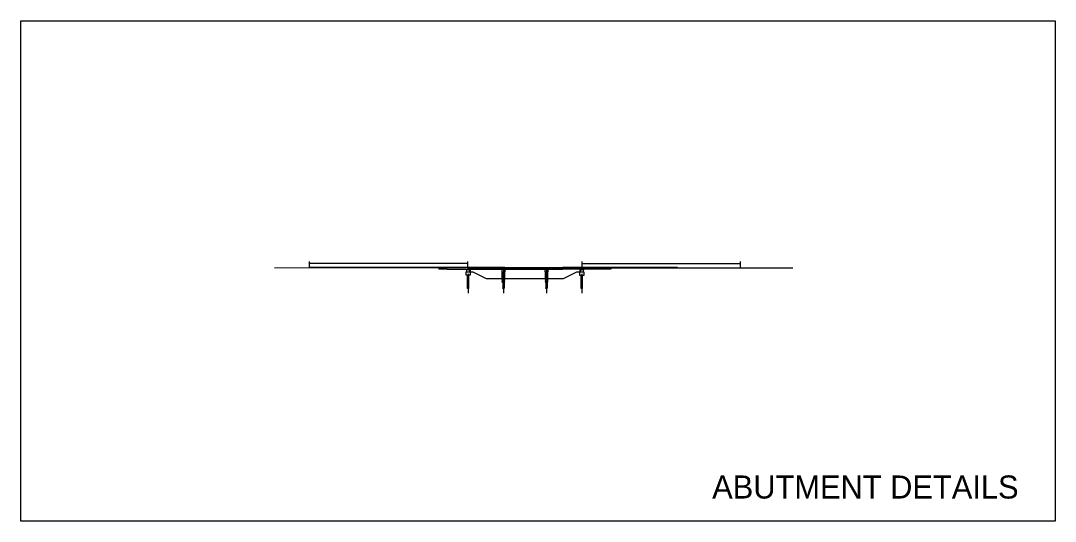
# Model space of a CAD drawing. Extents: x -2063 to 2068, y 79 to 1202.
# Drawn here: x 1170 to 2068, y 79 to 513 of the extents above; entities that cross this region are included whole.
import ezdxf

# ---------------------------------------------------------------- set-up
doc = ezdxf.new("R2010")
doc.units = 0
for name, color, linetype in [('BR_P_Gen_Joint_Filler', 7, 'Continuous'), ('BR_P_Slab_Object', 7, 'Continuous'), ('BR_X_Brg_Centerline', 7, 'Continuous'), ('BR_X_Gen_Approach_Slab', 7, 'Continuous'), ('BR_X_Slab_Object', 7, 'Continuous'), ('BR_X_Sub_Deep_Centerline', 7, 'Continuous'), ('BR_X_Sub_Deep_Object', 7, 'Continuous'), ('BR_X_Sub_Object', 7, 'Continuous'), ('PF_X_Ground_Line', 7, 'Continuous'), ('SC_Scratch1', 7, 'Continuous'), ('XS_P_Pavt_Surface', 7, 'Continuous')]:
    doc.layers.add(name, color=color, linetype=linetype)

msp = doc.modelspace()

# ---------------------------------------------------------------- linework, layer by layer
at = {"layer": 'BR_P_Gen_Joint_Filler'}
msp.add_line((1558.52, 298.6), (1558.67, 298.6), dxfattribs=at)
for points in [[(1558.46, 298.62), (1558.5, 298.62), (1558.5, 298.45), (1558.46, 298.45)], [(1657.78, 298.59), (1657.74, 298.59), (1657.74, 298.42), (1657.78, 298.42)]]:
    msp.add_lwpolyline(points, close=True, dxfattribs=at)
at = {"layer": 'BR_P_Slab_Object'}
for p, q in [((1558.52, 298.64), (1558.5, 298.62)), ((1558.5, 298.45), (1558.5, 298.62)), ((1657.72, 298.61), (1657.74, 298.59)), ((1657.74, 298.59), (1657.74, 298.42))]:
    msp.add_line(p, q, dxfattribs=at)
for points in [[(1640.62, 298.44), (1590.62, 298.46), (1558.5, 298.45)], [(1558.52, 298.64), (1590.62, 298.65), (1640.62, 298.63)]]:
    msp.add_lwpolyline(points, dxfattribs=at)
for centre, start in [((1635.98, -11316.67), 89.892735), ((1635.98, -11316.86), 89.892632)]:
    msp.add_arc(centre, 11615.3, start, 89.977082, dxfattribs=at)
at = {"layer": 'BR_X_Brg_Centerline'}
for p, q in [((1559.37, 299.37), (1559.37, 296.27)), ((1589.37, 298.1), (1589.37, 276.39)), ((1626.87, 298.08), (1626.87, 276.39)), ((1656.88, 299.35), (1656.88, 296.24))]:
    msp.add_line(p, q, dxfattribs=at)
at = {"layer": 'BR_X_Gen_Approach_Slab'}
for p, q in [((1533.5, 298.52), (1533.5, 297.44)), ((1558.5, 298.53), (1540.62, 298.53)), ((1540.62, 297.44), (1556.64, 297.45)), ((1556.64, 297.45), (1557.06, 297.03)), ((1557.06, 297.03), (1557.64, 297.03)), ((1682.74, 298.47), (1682.74, 297.39))]:
    msp.add_line(p, q, dxfattribs=at)
msp.add_lwpolyline([(1659.6, 297.42), (1659.19, 297.01), (1658.61, 297.01)], dxfattribs=at)
for centre, start, end in [((1603.12, -62201.63), 90.0572958, 90.0638229), ((1603.12, -62202.71), 90.0572958, 90.0638229), ((1578.12, -62201.63), 89.9040915, 89.9270098), ((1578.12, -62202.71), 89.9040915, 89.9253092)]:
    msp.add_arc(centre, 62500.19, start, end, dxfattribs=at)
at = {"layer": 'BR_X_Slab_Object'}
for p, q in [((1558.5, 298.53), (1558.5, 297.24)), ((1657.74, 297.22), (1657.74, 298.51))]:
    msp.add_line(p, q, dxfattribs=at)
for points in [[(1640.62, 298.61), (1590.62, 298.63), (1558.5, 298.62)], [(1640.62, 298.53), (1590.62, 298.55), (1558.5, 298.53)], [(1558.5, 298.51), (1590.62, 298.53), (1640.62, 298.51)], [(1640.62, 298.44), (1590.62, 298.46), (1558.5, 298.45)], [(1560.52, 297.24), (1590.62, 297.25), (1640.62, 297.23)]]:
    msp.add_lwpolyline(points, dxfattribs=at)
for centre, radius, start in [((1578.12, -62201.63), 62500.27, 89.9270099), ((1578.12, -62201.63), 62500.19, 89.9270098), ((1578.12, -62201.63), 62500.17, 89.9270098), ((1578.12, -62201.63), 62500.1, 89.9270097), ((1578.12, -62202.92), 62500.19, 89.9288623)]:
    msp.add_arc(centre, radius, start, 89.9427042, dxfattribs=at)
at = {"layer": 'BR_X_Sub_Deep_Centerline'}
for p, q in [((1558.79, 293.16), (1558.79, 276.39)), ((1657.45, 293.13), (1657.45, 276.39))]:
    msp.add_line(p, q, dxfattribs=at)
at = {"layer": 'BR_X_Sub_Deep_Object'}
for p, q in [((1558.21, 280.79), (1558.21, 291.97)), ((1559.38, 280.79), (1559.38, 291.97)), ((1588.79, 294.98), (1588.79, 280.79)), ((1589.96, 294.98), (1589.96, 280.79)), ((1626.29, 294.97), (1626.29, 280.79)), ((1627.46, 294.97), (1627.46, 280.79)), ((1656.87, 280.76), (1656.87, 291.94)), ((1658.04, 280.76), (1658.04, 291.94))]:
    msp.add_line(p, q, dxfattribs=at)
for points in [[(1588.29, 294.98), (1588.37, 294.97), (1588.37, 294.91), (1588.19, 294.88), (1588.19, 294.81), (1588.37, 294.78), (1588.37, 294.71), (1588.19, 294.68), (1588.19, 294.61), (1588.37, 294.58), (1588.37, 294.52), (1588.19, 294.49), (1588.19, 294.42), (1588.37, 294.39), (1588.37, 294.33), (1588.19, 294.3), (1588.19, 294.23), (1588.37, 294.2), (1588.37, 294.14), (1588.19, 294.11), (1588.19, 294.04), (1588.37, 294.01), (1588.37, 293.94), (1588.19, 293.91), (1588.19, 293.84), (1588.37, 293.81), (1588.37, 293.75), (1588.19, 293.72), (1588.19, 293.65), (1588.37, 293.62), (1588.37, 293.56), (1588.19, 293.53), (1588.19, 293.46), (1588.37, 293.43), (1588.37, 293.36), (1588.19, 293.33), (1588.19, 293.26), (1588.37, 293.23), (1588.37, 293.17), (1588.19, 293.14), (1588.19, 293.07), (1588.37, 293.04), (1588.37, 292.98), (1588.19, 292.95), (1588.19, 292.88), (1588.37, 292.85), (1588.37, 292.78), (1588.19, 292.75), (1588.19, 292.68), (1588.37, 292.65), (1588.37, 292.59), (1588.19, 292.56), (1588.19, 292.49), (1588.37, 292.46), (1588.37, 292.4), (1588.19, 292.37), (1588.19, 292.3), (1588.37, 292.27), (1588.37, 292.2), (1588.19, 292.17), (1588.19, 292.1), (1588.37, 292.07), (1588.37, 292.01), (1588.19, 291.98), (1588.19, 291.91), (1588.37, 291.88), (1588.37, 291.82), (1588.19, 291.79), (1588.19, 291.72), (1588.37, 291.69), (1588.37, 291.62), (1588.19, 291.59), (1588.19, 291.52), (1588.37, 291.49), (1588.37, 291.43), (1588.19, 291.4), (1588.19, 291.33), (1588.37, 291.3), (1588.37, 291.24), (1588.19, 291.21), (1588.19, 291.14), (1588.37, 291.11), (1588.37, 291.04), (1588.19, 291.01), (1588.19, 290.94), (1588.37, 290.91), (1588.37, 290.85), (1588.19, 290.82), (1588.19, 290.75), (1588.37, 290.72), (1588.37, 290.66), (1588.19, 290.63), (1588.19, 290.56), (1588.37, 290.53), (1588.37, 290.46), (1588.19, 290.43), (1588.19, 290.36), (1588.37, 290.33), (1588.37, 290.27), (1588.19, 290.24), (1588.19, 290.17), (1588.37, 290.14), (1588.37, 290.08), (1588.19, 290.05), (1588.19, 289.98), (1588.37, 289.95), (1588.37, 289.88), (1588.19, 289.85), (1588.19, 289.78), (1588.37, 289.75), (1588.37, 289.69), (1588.19, 289.66), (1588.19, 289.59), (1588.37, 289.56), (1588.37, 289.5), (1588.19, 289.47), (1588.19, 289.4), (1588.37, 289.37), (1588.37, 289.3), (1588.19, 289.27), (1588.19, 289.2), (1588.37, 289.17), (1588.37, 289.11), (1588.19, 289.08), (1588.19, 289.01), (1588.37, 288.98), (1588.37, 288.92), (1588.19, 288.89), (1588.19, 288.82), (1588.37, 288.79), (1588.37, 288.72), (1588.19, 288.69), (1588.19, 288.62), (1588.37, 288.59), (1588.37, 288.53), (1588.19, 288.5), (1588.19, 288.43), (1588.37, 288.4), (1588.37, 288.34), (1588.19, 288.31), (1588.19, 288.24), (1588.37, 288.21), (1588.37, 288.14), (1588.19, 288.11), (1588.19, 288.04), (1588.37, 288.01), (1588.37, 287.95), (1588.19, 287.92), (1588.19, 287.85), (1588.37, 287.82), (1588.37, 287.76), (1588.19, 287.73), (1588.19, 287.66), (1588.37, 287.63), (1588.37, 287.56), (1588.19, 287.53), (1588.19, 287.46), (1588.37, 287.43), (1588.37, 287.37), (1588.19, 287.34), (1588.19, 287.27), (1588.37, 287.24), (1588.37, 287.18), (1588.19, 287.15), (1588.19, 287.08), (1588.37, 287.05), (1588.37, 286.98), (1588.19, 286.95), (1588.19, 286.88), (1588.37, 286.85), (1588.37, 286.79), (1588.19, 286.76), (1588.19, 286.69), (1588.37, 286.66), (1588.37, 286.6), (1588.19, 286.57), (1588.19, 286.5), (1588.37, 286.47), (1588.37, 286.4), (1588.19, 286.37), (1588.19, 286.3), (1588.37, 286.27), (1588.37, 286.21), (1588.19, 286.18), (1588.19, 286.17), (1590.55, 286.17), (1590.55, 286.18), (1590.37, 286.21), (1590.37, 286.27), (1590.55, 286.3), (1590.55, 286.37), (1590.37, 286.4), (1590.37, 286.47), (1590.55, 286.5), (1590.55, 286.57), (1590.37, 286.6), (1590.37, 286.66), (1590.55, 286.69), (1590.55, 286.76), (1590.37, 286.79), (1590.37, 286.85), (1590.55, 286.88), (1590.55, 286.95), (1590.37, 286.98), (1590.37, 287.05), (1590.55, 287.08), (1590.55, 287.15), (1590.37, 287.18), (1590.37, 287.24), (1590.55, 287.27), (1590.55, 287.34), (1590.37, 287.37), (1590.37, 287.43), (1590.55, 287.46), (1590.55, 287.53), (1590.37, 287.56), (1590.37, 287.63), (1590.55, 287.66), (1590.55, 287.73), (1590.37, 287.76), (1590.37, 287.82), (1590.55, 287.85), (1590.55, 287.92), (1590.37, 287.95), (1590.37, 288.01), (1590.55, 288.04), (1590.55, 288.11), (1590.37, 288.14), (1590.37, 288.21), (1590.55, 288.24), (1590.55, 288.31), (1590.37, 288.34), (1590.37, 288.4), (1590.55, 288.43), (1590.55, 288.5), (1590.37, 288.53), (1590.37, 288.59), (1590.55, 288.62), (1590.55, 288.69), (1590.37, 288.72), (1590.37, 288.79), (1590.55, 288.82), (1590.55, 288.89), (1590.37, 288.92), (1590.37, 288.98), (1590.55, 289.01), (1590.55, 289.08), (1590.37, 289.11), (1590.37, 289.17), (1590.55, 289.2), (1590.55, 289.27), (1590.37, 289.3), (1590.37, 289.37), (1590.55, 289.4), (1590.55, 289.47), (1590.37, 289.5), (1590.37, 289.56), (1590.55, 289.59), (1590.55, 289.66), (1590.37, 289.69), (1590.37, 289.75), (1590.55, 289.78), (1590.55, 289.85), (1590.37, 289.88), (1590.37, 289.95), (1590.55, 289.98), (1590.55, 290.05), (1590.37, 290.08), (1590.37, 290.14), (1590.55, 290.17), (1590.55, 290.24), (1590.37, 290.27), (1590.37, 290.33), (1590.55, 290.36), (1590.55, 290.43), (1590.37, 290.46), (1590.37, 290.53), (1590.55, 290.56), (1590.55, 290.63), (1590.37, 290.66), (1590.37, 290.72), (1590.55, 290.75), (1590.55, 290.82), (1590.37, 290.85), (1590.37, 290.91), (1590.55, 290.94), (1590.55, 291.01), (1590.37, 291.04), (1590.37, 291.11), (1590.55, 291.14), (1590.55, 291.21), (1590.37, 291.24), (1590.37, 291.3), (1590.55, 291.33), (1590.55, 291.4), (1590.37, 291.43), (1590.37, 291.49), (1590.55, 291.52), (1590.55, 291.59), (1590.37, 291.62), (1590.37, 291.69), (1590.55, 291.72), (1590.55, 291.79), (1590.37, 291.82), (1590.37, 291.88), (1590.55, 291.91), (1590.55, 291.98), (1590.37, 292.01), (1590.37, 292.07), (1590.55, 292.1), (1590.55, 292.17), (1590.37, 292.2), (1590.37, 292.27), (1590.55, 292.3), (1590.55, 292.37), (1590.37, 292.4), (1590.37, 292.46), (1590.55, 292.49), (1590.55, 292.56), (1590.37, 292.59), (1590.37, 292.65), (1590.55, 292.68), (1590.55, 292.75), (1590.37, 292.78), (1590.37, 292.85), (1590.55, 292.88), (1590.55, 292.95), (1590.37, 292.98), (1590.37, 293.04), (1590.55, 293.07), (1590.55, 293.14), (1590.37, 293.17), (1590.37, 293.23), (1590.55, 293.26), (1590.55, 293.33), (1590.37, 293.36), (1590.37, 293.43), (1590.55, 293.46), (1590.55, 293.53), (1590.37, 293.56), (1590.37, 293.62), (1590.55, 293.65), (1590.55, 293.72), (1590.37, 293.75), (1590.37, 293.81), (1590.55, 293.84), (1590.55, 293.91), (1590.37, 293.94), (1590.37, 294.01), (1590.55, 294.04), (1590.55, 294.11), (1590.37, 294.14), (1590.37, 294.2), (1590.55, 294.23), (1590.55, 294.3), (1590.37, 294.33), (1590.37, 294.39), (1590.55, 294.42), (1590.55, 294.49), (1590.37, 294.52), (1590.37, 294.58), (1590.55, 294.61), (1590.55, 294.68), (1590.37, 294.71), (1590.37, 294.78), (1590.55, 294.81), (1590.55, 294.88), (1590.37, 294.91), (1590.37, 294.97), (1590.45, 294.98)], [(1625.87, 294.97), (1625.87, 294.91), (1625.69, 294.88), (1625.69, 294.81), (1625.87, 294.78), (1625.87, 294.71), (1625.69, 294.68), (1625.69, 294.61), (1625.87, 294.58), (1625.87, 294.52), (1625.69, 294.49), (1625.69, 294.42), (1625.87, 294.39), (1625.87, 294.33), (1625.69, 294.3), (1625.69, 294.23), (1625.87, 294.2), (1625.87, 294.14), (1625.69, 294.11), (1625.69, 294.04), (1625.87, 294.01), (1625.87, 293.94), (1625.69, 293.91), (1625.69, 293.84), (1625.87, 293.81), (1625.87, 293.75), (1625.69, 293.72), (1625.69, 293.65), (1625.87, 293.62), (1625.87, 293.56), (1625.69, 293.53), (1625.69, 293.46), (1625.87, 293.43), (1625.87, 293.36), (1625.69, 293.33), (1625.69, 293.26), (1625.87, 293.23), (1625.87, 293.17), (1625.69, 293.14), (1625.69, 293.07), (1625.87, 293.04), (1625.87, 292.98), (1625.69, 292.95), (1625.69, 292.88), (1625.87, 292.85), (1625.87, 292.78), (1625.69, 292.75), (1625.69, 292.68), (1625.87, 292.65), (1625.87, 292.59), (1625.69, 292.56), (1625.69, 292.49), (1625.87, 292.46), (1625.87, 292.4), (1625.69, 292.37), (1625.69, 292.3), (1625.87, 292.27), (1625.87, 292.2), (1625.69, 292.17), (1625.69, 292.1), (1625.87, 292.07), (1625.87, 292.01), (1625.69, 291.98), (1625.69, 291.91), (1625.87, 291.88), (1625.87, 291.82), (1625.69, 291.79), (1625.69, 291.72), (1625.87, 291.69), (1625.87, 291.62), (1625.69, 291.59), (1625.69, 291.52), (1625.87, 291.49), (1625.87, 291.43), (1625.69, 291.4), (1625.69, 291.33), (1625.87, 291.3), (1625.87, 291.24), (1625.69, 291.21), (1625.69, 291.14), (1625.87, 291.11), (1625.87, 291.04), (1625.69, 291.01), (1625.69, 290.94), (1625.87, 290.91), (1625.87, 290.85), (1625.69, 290.82), (1625.69, 290.75), (1625.87, 290.72), (1625.87, 290.66), (1625.69, 290.63), (1625.69, 290.56), (1625.87, 290.53), (1625.87, 290.46), (1625.69, 290.43), (1625.69, 290.36), (1625.87, 290.33), (1625.87, 290.27), (1625.69, 290.24), (1625.69, 290.17), (1625.87, 290.14), (1625.87, 290.08), (1625.69, 290.05), (1625.69, 289.98), (1625.87, 289.95), (1625.87, 289.88), (1625.69, 289.85), (1625.69, 289.78), (1625.87, 289.75), (1625.87, 289.69), (1625.69, 289.66), (1625.69, 289.59), (1625.87, 289.56), (1625.87, 289.5), (1625.69, 289.47), (1625.69, 289.4), (1625.87, 289.37), (1625.87, 289.3), (1625.69, 289.27), (1625.69, 289.2), (1625.87, 289.17), (1625.87, 289.11), (1625.69, 289.08), (1625.69, 289.01), (1625.87, 288.98), (1625.87, 288.92), (1625.69, 288.89), (1625.69, 288.82), (1625.87, 288.79), (1625.87, 288.72), (1625.69, 288.69), (1625.69, 288.62), (1625.87, 288.59), (1625.87, 288.53), (1625.69, 288.5), (1625.69, 288.43), (1625.87, 288.4), (1625.87, 288.34), (1625.69, 288.31), (1625.69, 288.24), (1625.87, 288.21), (1625.87, 288.14), (1625.69, 288.11), (1625.69, 288.04), (1625.87, 288.01), (1625.87, 287.95), (1625.69, 287.92), (1625.69, 287.85), (1625.87, 287.82), (1625.87, 287.76), (1625.69, 287.73), (1625.69, 287.66), (1625.87, 287.63), (1625.87, 287.56), (1625.69, 287.53), (1625.69, 287.46), (1625.87, 287.43), (1625.87, 287.37), (1625.69, 287.34), (1625.69, 287.27), (1625.87, 287.24), (1625.87, 287.18), (1625.69, 287.15), (1625.69, 287.08), (1625.87, 287.05), (1625.87, 286.98), (1625.69, 286.95), (1625.69, 286.88), (1625.87, 286.85), (1625.87, 286.79), (1625.69, 286.76), (1625.69, 286.69), (1625.87, 286.66), (1625.87, 286.6), (1625.69, 286.57), (1625.69, 286.5), (1625.87, 286.47), (1625.87, 286.4), (1625.69, 286.37), (1625.69, 286.3), (1625.87, 286.27), (1625.87, 286.21), (1625.69, 286.18), (1625.69, 286.17), (1628.05, 286.17), (1628.05, 286.18), (1627.87, 286.21), (1627.87, 286.27), (1628.05, 286.3), (1628.05, 286.37), (1627.87, 286.4), (1627.87, 286.47), (1628.05, 286.5), (1628.05, 286.57), (1627.87, 286.6), (1627.87, 286.66), (1628.05, 286.69), (1628.05, 286.76), (1627.87, 286.79), (1627.87, 286.85), (1628.05, 286.88), (1628.05, 286.95), (1627.87, 286.98), (1627.87, 287.05), (1628.05, 287.08), (1628.05, 287.15), (1627.87, 287.18), (1627.87, 287.24), (1628.05, 287.27), (1628.05, 287.34), (1627.87, 287.37), (1627.87, 287.43), (1628.05, 287.46), (1628.05, 287.53), (1627.87, 287.56), (1627.87, 287.63), (1628.05, 287.66), (1628.05, 287.73), (1627.87, 287.76), (1627.87, 287.82), (1628.05, 287.85), (1628.05, 287.92), (1627.87, 287.95), (1627.87, 288.01), (1628.05, 288.04), (1628.05, 288.11), (1627.87, 288.14), (1627.87, 288.21), (1628.05, 288.24), (1628.05, 288.31), (1627.87, 288.34), (1627.87, 288.4), (1628.05, 288.43), (1628.05, 288.5), (1627.87, 288.53), (1627.87, 288.59), (1628.05, 288.62), (1628.05, 288.69), (1627.87, 288.72), (1627.87, 288.79), (1628.05, 288.82), (1628.05, 288.89), (1627.87, 288.92), (1627.87, 288.98), (1628.05, 289.01), (1628.05, 289.08), (1627.87, 289.11), (1627.87, 289.17), (1628.05, 289.2), (1628.05, 289.27), (1627.87, 289.3), (1627.87, 289.37), (1628.05, 289.4), (1628.05, 289.47), (1627.87, 289.5), (1627.87, 289.56), (1628.05, 289.59), (1628.05, 289.66), (1627.87, 289.69), (1627.87, 289.75), (1628.05, 289.78), (1628.05, 289.85), (1627.87, 289.88), (1627.87, 289.95), (1628.05, 289.98), (1628.05, 290.05), (1627.87, 290.08), (1627.87, 290.14), (1628.05, 290.17), (1628.05, 290.24), (1627.87, 290.27), (1627.87, 290.33), (1628.05, 290.36), (1628.05, 290.43), (1627.87, 290.46), (1627.87, 290.53), (1628.05, 290.56), (1628.05, 290.63), (1627.87, 290.66), (1627.87, 290.72), (1628.05, 290.75), (1628.05, 290.82), (1627.87, 290.85), (1627.87, 290.91), (1628.05, 290.94), (1628.05, 291.01), (1627.87, 291.04), (1627.87, 291.11), (1628.05, 291.14), (1628.05, 291.21), (1627.87, 291.24), (1627.87, 291.3), (1628.05, 291.33), (1628.05, 291.4), (1627.87, 291.43), (1627.87, 291.49), (1628.05, 291.52), (1628.05, 291.59), (1627.87, 291.62), (1627.87, 291.69), (1628.05, 291.72), (1628.05, 291.79), (1627.87, 291.82), (1627.87, 291.88), (1628.05, 291.91), (1628.05, 291.98), (1627.87, 292.01), (1627.87, 292.07), (1628.05, 292.1), (1628.05, 292.17), (1627.87, 292.2), (1627.87, 292.27), (1628.05, 292.3), (1628.05, 292.37), (1627.87, 292.4), (1627.87, 292.46), (1628.05, 292.49), (1628.05, 292.56), (1627.87, 292.59), (1627.87, 292.65), (1628.05, 292.68), (1628.05, 292.75), (1627.87, 292.78), (1627.87, 292.85), (1628.05, 292.88), (1628.05, 292.95), (1627.87, 292.98), (1627.87, 293.04), (1628.05, 293.07), (1628.05, 293.14), (1627.87, 293.17), (1627.87, 293.23), (1628.05, 293.26), (1628.05, 293.33), (1627.87, 293.36), (1627.87, 293.43), (1628.05, 293.46), (1628.05, 293.53), (1627.87, 293.56), (1627.87, 293.62), (1628.05, 293.65), (1628.05, 293.72), (1627.87, 293.75), (1627.87, 293.81), (1628.05, 293.84), (1628.05, 293.91), (1627.87, 293.94), (1627.87, 294.01), (1628.05, 294.04), (1628.05, 294.11), (1627.87, 294.14), (1627.87, 294.2), (1628.05, 294.23), (1628.05, 294.3), (1627.87, 294.33), (1627.87, 294.39), (1628.05, 294.42), (1628.05, 294.49), (1627.87, 294.52), (1627.87, 294.58), (1628.05, 294.61), (1628.05, 294.68), (1627.87, 294.71), (1627.87, 294.78), (1628.05, 294.81), (1628.05, 294.88), (1627.87, 294.91), (1627.87, 294.97)]]:
    msp.add_lwpolyline(points, dxfattribs=at)
for centre, radius in [((1558.5, 280.79), 0.29), ((1589.08, 280.79), 0.292), ((1626.58, 280.79), 0.292), ((1657.16, 280.76), 0.29)]:
    msp.add_circle(centre, radius, dxfattribs=at)
for centre, radius in [((1559.08, 280.79), 0.293), ((1589.66, 280.79), 0.292), ((1627.16, 280.79), 0.292), ((1657.75, 280.76), 0.293)]:
    msp.add_arc(centre, radius, 180, 0, dxfattribs=at)
at = {"layer": 'BR_X_Sub_Object'}
for p, q in [((1557.64, 294.97), (1557.64, 297.24)), ((1557.64, 297.24), (1558.5, 297.24)), ((1558.5, 297.24), (1558.5, 297.03)), ((1558.5, 297.03), (1559.22, 297.03)), ((1559.95, 297.24), (1560.52, 297.24)), ((1559.95, 297.24), (1559.95, 294.97)), ((1560.52, 297.24), (1560.52, 294.97)), ((1557.06, 291.97), (1557.06, 294.97)), ((1557.06, 294.97), (1560.52, 294.97)), ((1560.52, 291.97), (1557.06, 291.97)), ((1560.52, 294.97), (1560.52, 291.97)), ((1655.72, 291.94), (1655.72, 294.94)), ((1655.72, 294.94), (1659.19, 294.94)), ((1659.19, 291.94), (1655.72, 291.94)), ((1659.19, 291.94), (1655.72, 291.94)), ((1659.19, 294.94), (1659.19, 291.94)), ((1659.19, 291.97), (1659.19, 291.94))]:
    msp.add_line(p, q, dxfattribs=at)
for points in [[(1559.22, 297.03), (1559.22, 297.24), (1559.95, 297.24)], [(1587.93, 297.25), (1587.93, 294.98), (1590.82, 294.98), (1590.82, 297.25)], [(1625.43, 297.24), (1625.43, 294.97), (1628.32, 294.97), (1628.32, 297.24)], [(1656.3, 297.22), (1655.72, 297.22), (1655.72, 294.94)], [(1656.3, 294.94), (1656.3, 297.22), (1657.02, 297.22), (1657.02, 297.01), (1657.74, 297.01), (1657.74, 297.22), (1658.61, 297.22), (1658.61, 294.94)]]:
    msp.add_lwpolyline(points, dxfattribs=at)
at = {"layer": 'PF_X_Ground_Line'}
for p, q in [((1390.62, 298.52), (1440.62, 298.68)), ((1740.62, 298.68), (1790.62, 298.52)), ((1560.52, 294.97), (1562.95, 294.97)), ((1562.95, 294.97), (1574.55, 289.17)), ((1574.55, 289.17), (1641.7, 289.17)), ((1641.7, 289.17), (1653.24, 294.94)), ((1653.24, 294.94), (1655.72, 294.94))]:
    msp.add_line(p, q, dxfattribs=at)
msp.add_lwpolyline([(1540.62, 298.86), (1590.62, 298.88), (1640.62, 298.86)], dxfattribs=at)
for centre, radius, start, end in [((1603.12, -62201.57), 62500.46, 90.1031323, 90.1489687), ((1603.12, -62201.3), 62500.19, 90.0638229, 90.1031323), ((1542.79, -5120.04), 5418.9, 90.02292, 90.0982), ((1635.98, -11316.44), 11615.3, 89.892632, 89.977082), ((1578.12, -62201.3), 62500.19, 89.8968677, 89.9270098), ((1578.12, -62201.57), 62500.46, 89.8510313, 89.8968677), ((2028.12, 62799.15), 62501.09, 269.7822771, 269.8281131)]:
    msp.add_arc(centre, radius, start, end, dxfattribs=at)
at = {"layer": 'SC_Scratch1'}
for p, q in [((1421, 298.55), (1421, 303.95)), ((1421, 302.39), (1558.5, 302.39)), ((1558.5, 298.62), (1558.5, 303.95)), ((1561.03, 298.53), (1561.03, 298.78)), ((1657.74, 298.59), (1657.74, 303.87)), ((1657.74, 302.32), (1795.24, 302.32)), ((1795.24, 298.5), (1795.24, 303.87))]:
    msp.add_line(p, q, dxfattribs=at)
msp.add_lwpolyline([(1170.42, 512.75), (2068.47, 512.75), (2068.47, 78.7), (1170.42, 78.7)], close=True, dxfattribs=at)
at = {"layer": 'XS_P_Pavt_Surface'}
for p, q in [((1558.44, 298.64), (1421, 298.62)), ((1421, 298.62), (1421, 298.49)), ((1558.5, 298.51), (1421, 298.49)), ((1558.44, 298.64), (1558.46, 298.62)), ((1657.74, 298.49), (1795.24, 298.38)), ((1657.8, 298.61), (1657.78, 298.59)), ((1657.8, 298.61), (1795.24, 298.5)), ((1795.24, 298.5), (1795.24, 298.38))]:
    msp.add_line(p, q, dxfattribs=at)

# ---------------------------------------------------------------- texts
at = {"layer": 'SC_Scratch1'}
msp.add_text('ABUTMENT DETAILS', height=20, dxfattribs=at).set_placement((1770.61, 98.43))

doc.saveas('drawing.dxf')
